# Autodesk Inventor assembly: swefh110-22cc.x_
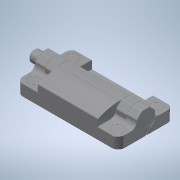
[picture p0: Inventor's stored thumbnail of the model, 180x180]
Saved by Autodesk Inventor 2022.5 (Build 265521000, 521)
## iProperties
Part Number: swefh110-22cc.x_
Material: 一般
Document SubType Name: Assembly
Designer: ImaoCorp
Sending System: SOLIDWORKS 2017-2017317
MC: AMD64
MC_MODEL: Intel64 Family 6 Model 60 Stepping 3, GenuineIntel
OS: Windows_NT
FRU: Parasolid Version 29.0, build 201,  4-17-2017
FORMAT: text
GUISE: transmit
KEY: swefh110-22cc
FILE: swefh110-22cc.x_t
DATE: Wed Sep 18 16:02:29 2019
Author: ImaoCorp
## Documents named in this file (3)
- X:\14_SW2022-Inv2022\00_全2023-1023新製品(TCC)まで\s\swefh110-22cc\SWEFH110-22CC.iam
- X:\14_SW2022-Inv2022\00_全2023-1023新製品(TCC)まで\s\swefh110-22cc\swefh110-22cc_01.ipt
- X:\14_SW2022-Inv2022\00_全2023-1023新製品(TCC)まで\s\swefh110-22cc\swefh110-22cc_02.ipt
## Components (2 placed, 2 different names)
1. swefh110-22cc_01
2. swefh110-22cc_02
